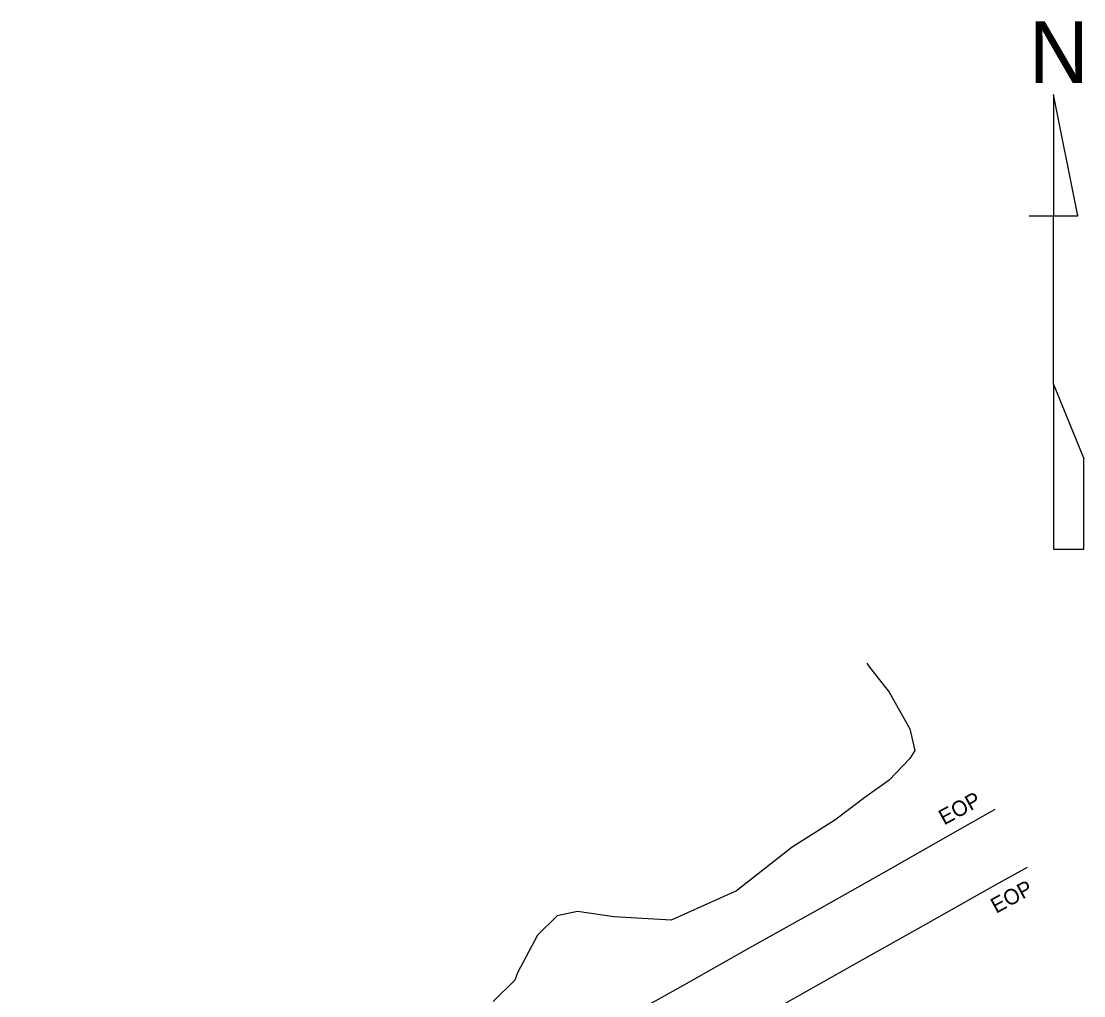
# Model space of a CAD drawing. Extents: x 2076109 to 2080761, y 592812 to 596750.
# Drawn here: x 2077866 to 2078209.5, y 596219.9 to 596535 of the extents above; entities that cross this region are included whole.
import ezdxf

# ---------------------------------------------------------------- set-up
doc = ezdxf.new("R2010")
doc.units = 0
for name, color, linetype in [('RD_EX_Misc', 7, 'Continuous'), ('RD_EX_Road', 7, 'Continuous'), ('RD_EX_Road_txCode', 7, 'Continuous'), ('RD_EX_VEG', 7, 'Continuous')]:
    doc.layers.add(name, color=color, linetype=linetype)

msp = doc.modelspace()

# ---------------------------------------------------------------- linework, layer by layer
at = {"layer": 'RD_EX_Misc'}
for p, q in [((2078207.52, 596472.14), (2078199.68, 596511.34)), ((2078199.68, 596511.34), (2078199.68, 596511.34)), ((2078199.68, 596511.34), (2078199.68, 596472.14)), ((2078207.52, 596472.14), (2078199.68, 596511.34)), ((2078199.68, 596511.34), (2078199.68, 596511.34)), ((2078199.68, 596511.34), (2078199.68, 596472.14)), ((2078191.84, 596472.14), (2078199.68, 596472.14)), ((2078191.84, 596472.14), (2078199.68, 596472.14)), ((2078199.68, 596417.75), (2078199.68, 596472.14)), ((2078199.68, 596472.14), (2078207.52, 596472.14)), ((2078199.68, 596417.75), (2078199.68, 596472.14)), ((2078199.68, 596472.14), (2078207.52, 596472.14)), ((2078207.52, 596472.14), (2078207.52, 596472.61)), ((2078207.52, 596472.14), (2078207.52, 596472.61)), ((2078209.48, 596393.74), (2078199.68, 596417.75)), ((2078199.68, 596417.75), (2078199.68, 596364.34)), ((2078209.48, 596393.74), (2078199.68, 596417.75)), ((2078199.68, 596417.75), (2078199.68, 596364.34)), ((2078209.48, 596364.34), (2078209.48, 596394.01)), ((2078209.48, 596394.01), (2078209.48, 596393.74)), ((2078209.48, 596364.34), (2078209.48, 596394.01)), ((2078209.48, 596394.01), (2078209.48, 596393.74)), ((2078199.68, 596364.34), (2078209.48, 596364.34)), ((2078199.68, 596364.34), (2078209.48, 596364.34))]:
    msp.add_line(p, q, dxfattribs=at)
at = {"layer": 'RD_EX_Road'}
for points in [[(2078180.71, 596280.19), (2078166.31, 596272.02), (2078145.45, 596260.13), (2078125.48, 596248.81), (2078101.13, 596235.18), (2078080.21, 596223.38), (2078062.58, 596213.53)], [(2078180.71, 596280.19), (2078166.31, 596272.02), (2078145.45, 596260.13), (2078125.48, 596248.81), (2078101.13, 596235.18), (2078080.21, 596223.38), (2078062.58, 596213.53)], [(2077866, 596078.88), (2077882.82, 596088.5), (2077908.39, 596102.7), (2077940, 596120.34), (2077965.56, 596134.84), (2077993.91, 596150.64), (2078020.83, 596165.73), (2078053.47, 596183.92), (2078082.23, 596200.16), (2078111.12, 596216.43), (2078136.34, 596230.7), (2078157.72, 596242.66), (2078180, 596255.29), (2078191.26, 596261.54)], [(2077866, 596078.88), (2077882.82, 596088.5), (2077908.39, 596102.7), (2077940, 596120.34), (2077965.56, 596134.84), (2077993.91, 596150.64), (2078020.83, 596165.73), (2078053.47, 596183.92), (2078082.23, 596200.16), (2078111.12, 596216.43), (2078136.34, 596230.7), (2078157.72, 596242.66), (2078180, 596255.29), (2078191.26, 596261.54)]]:
    msp.add_lwpolyline(points, dxfattribs=at)
at = {"layer": 'RD_EX_VEG'}
msp.add_lwpolyline([(2078139.3, 596327.45), (2078139.84, 596326.62), (2078146.62, 596318.13), (2078153.28, 596306.23), (2078154.86, 596299.2), (2078153.28, 596296.68), (2078146.6, 596289.65), (2078138.7, 596284.01), (2078129.06, 596276.74), (2078115.24, 596268.02), (2078097.21, 596253.87), (2078076.09, 596244.35), (2078057.58, 596245.5), (2078045.79, 596247.2), (2078039.24, 596245.76), (2078032.88, 596239.56), (2078026.43, 596227.37), (2078025.53, 596225.01), (2078018.55, 596218.05)], dxfattribs=at)
msp.add_lwpolyline([(2078139.3, 596327.45), (2078139.84, 596326.62), (2078146.62, 596318.13), (2078153.28, 596306.23), (2078154.86, 596299.2), (2078153.28, 596296.68), (2078146.6, 596289.65), (2078138.7, 596284.01), (2078129.06, 596276.74), (2078115.24, 596268.02), (2078097.21, 596253.87), (2078076.09, 596244.35), (2078057.58, 596245.5), (2078045.79, 596247.2), (2078039.24, 596245.76), (2078032.88, 596239.56), (2078026.43, 596227.37), (2078025.53, 596225.01), (2078018.55, 596218.05)], dxfattribs=at)

# ---------------------------------------------------------------- texts
at = {"layer": 'RD_EX_Misc'}
msp.add_text('N', height=20, rotation=360, dxfattribs=at).set_placement((2078191.78, 596515.05))
msp.add_text('N', height=20, rotation=360, dxfattribs=at).set_placement((2078191.78, 596515.05))
at = {"layer": 'RD_EX_Road_txCode'}
for p in [(2078164.33, 596274.99), (2078164.33, 596274.99), (2078181.14, 596246.42), (2078181.14, 596246.42)]:
    msp.add_text('EOP', height=5, rotation=28.5196, dxfattribs=at).set_placement(p)

doc.saveas('drawing.dxf')
